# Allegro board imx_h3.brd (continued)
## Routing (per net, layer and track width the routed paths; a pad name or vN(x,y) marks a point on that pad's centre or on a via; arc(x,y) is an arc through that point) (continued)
LCD_D11_EMI: length 2.2
  TOP w0.1: J13.84 95.82,75.54 FL5.10
LCD_D12: length 81.3
  TOP w0.1: FL4.3 88.27,76.77 88.27,76.77 85.9,76.77 85.27,77.39 85.27,77.41 v1(84.99,77.41) ; v1(84.23,79.81) 84.2,79.81 83.8,80.22 83.8,80.45 83.58,80.67 83.58,81.72 84.13,82.27 RN7.5
  INT1 w0.1: v1(84.99,77.41) 84.09,77.41 83.74,77.06 83.74,71.46 80.49,68.22 80.19,68.22 79.69,68.22 79.07,68.22 78.24,67.38 77.03,67.38 76.68,67.03 76.68,66.87 75.69,65.88 75.59,65.88 75.59,65.87 75.25,65.87 75.25,65.88 66.71,65.88 66.71,65.87 66.13,65.87 65.98,65.87 65.74,65.87 65.39,65.87 65.38,65.87 61.93,65.87 61.6,65.87 60.6,65.87 60.01,65.87 56.9,68.99 53.15,68.99 52.67,68.51 v1(52.67,68.14) ; v1(51.05,63.58) 51.05,63.26 48.48,60.69 48.48,59.44 47.95,58.91 47.95,56.62 49.26,55.31 49.26,54.81 49.26,53.67 49.64,53.28 v1(49.74,53.28)
  BOTTOM w0.1: v1(51.05,63.58) 51.05,63.77 52.09,64.81 52.09,65.15 52.33,65.39 52.33,65.42 52.67,65.77 v1(52.67,68.14) ; v1(84.99,77.41) 84.95,77.41 84.7,77.66 84.7,78.44 84.23,78.92 v1(84.23,79.81) ; v1(49.74,53.28) 49.81,53.28 49.85,53.24 50.24,53.24
LCD_D12_EMI: length 2.5
  TOP w0.1: FL4.7 94.09,76.77 94.72,76.15 95.9,76.15 J13.86
LCD_D13: length 85.5
  TOP w0.1: v1(84.17,78.04) 85.05,78.04 86.12,76.97 88.18,76.97 88.19,76.97 92.46,76.97 92.5,77.01 92.58,77.01 FL4.4 ; v1(84.03,80.79) 84.03,81.35 84.63,81.95 RN7.6
  INT1 w0.1: v1(45.5,62.81) 45.53,62.78 45.61,62.78 50.92,68.09 50.98,68.09 51.21,68.32 51.21,68.38 52.22,69.38 56.82,69.38 56.82,69.39 57.06,69.39 60.17,66.27 60.77,66.27 61.43,66.27 61.76,66.27 66.55,66.27 66.55,66.28 74.76,66.28 74.77,66.28 74.85,66.28 75.25,66.68 76.13,66.68 76.38,66.93 76.38,67.01 76.95,67.58 78.16,67.58 78.99,68.41 79.61,68.41 80.41,68.42 83.54,71.55 83.54,77.41 v1(84.17,78.04)
  BOTTOM w0.1: v1(84.03,80.79) 83.83,80.58 83.83,78.39 v1(84.17,78.04) ; v1(45.5,62.81) 45.48,62.81 45.48,62.78 47.72,62.78 49.77,60.72 49.77,58.96 49.47,58.66 49.47,57.4 49.83,57.05 49.83,57.05 50.73,56.16 50.73,53.6 51.05,53.28 51.05,53.24
LCD_D13_EMI: length 2.4
  TOP w0.1: J13.88 95.7,76.84 94.71,76.84 94.38,77.17 FL4.8
LCD_D14: length 83
  TOP w0.1: FL4.5 91.79,77.57 91.59,77.38 v1(91.48,77.38) 91.32,77.21 88.45,77.21 86.64,79.02 86.64,80.17 85.13,81.69 RN7.7
  INT1 w0.1: v1(90.32,68.65) 90.25,68.58 86.95,68.58 85.31,66.94 85.11,66.94 81.84,63.67 81.2,63.67 80.2,63.67 79.58,63.05 78.64,63.05 78.4,62.81 78.06,62.81 78.06,62.81 77.37,62.81 77.37,62.81 76.75,62.81 76.75,62.81 75.61,62.81 75.61,62.81 74.53,62.81 74.53,62.81 73.2,62.81 73.2,62.81 71.65,62.81 71.65,62.81 70.66,62.81 70.66,62.81 61.04,62.81 61.04,62.81 59.38,62.81 59.38,62.81 58.96,62.81 58.96,62.81 58.37,62.81 57.5,63.67 57.49,63.67 57.25,63.91 54.08,63.91 52.9,65.09 51.2,65.09 49,62.89 48.85,62.89 v1(48.71,62.75)
  BOTTOM w0.1: v1(91.48,77.38) 91.12,77.02 91.12,70.53 90.67,70.07 90.67,69.12 90.37,68.82 90.37,68.7 v1(90.32,68.65) ; 51.05,54.03 51.03,54.04 51.03,56.13 49.92,57.25 49.91,57.25 49.67,57.49 49.67,58.57 49.98,58.87 49.98,61.48 v1(48.71,62.75)
LCD_D14_EMI: length 2.4
  TOP w0.1: J13.90 95.7,77.34 94.71,77.34 94.68,77.37 94.27,77.37 94.07,77.57 FL4.9
LCD_D15: length 73.9
  TOP w0.1: FL4.6 91.01,77.97 90.77,77.72 v1(90.77,77.62) 90.62,77.47 88.48,77.47 86.84,79.1 86.84,80.26 85.68,81.42 RN7.8
  INT1 w0.1: v1(52.19,58.96) 52.2,58.97 54.34,58.97 55.71,60.34 55.74,60.38 55.85,60.49 57.09,60.49 58.2,61.6 58.72,61.6 59.1,61.6 59.21,61.6 59.62,61.6 59.88,61.6 59.88,61.61 60.54,61.61 60.54,61.6 73.7,61.6 73.7,61.61 74.03,61.61 74.03,61.6 78,61.6 78.28,61.33 78.61,61.33 79.27,61.33 80.61,62.67 81.2,62.67 81.6,62.67 82.26,62.67 82.97,63.38 84.06,63.38 85.4,64.72 v1(85.4,64.75)
  BOTTOM w0.1: v1(52.19,58.96) 52.16,58.93 52.16,58.16 51.43,57.43 51.43,55.49 51.84,55.08 U1.U3 ; v1(90.77,77.62) 90.74,77.62 90.71,77.59 90.71,70.64 89.74,69.67 89.74,69.14 85.4,64.79 v1(85.4,64.75)
LCD_D15_EMI: length 2.4
  TOP w0.1: FL4.10 94.12,77.97 94.51,77.59 95.87,77.59 J13.92
LCD_D16: length 75.5
  TOP w0.1: RN6.1 87.04,89.4 87.04,79.19 88.56,77.67 89.61,77.67 90.09,78.15 v1(90.12,78.15) 90.13,78.15 90.46,78.48 91.66,78.48 92.38,79.2 92.75,79.2
  INT1 w0.1: v1(51.69,58.41) 51.69,58.43 51.58,58.54 51.58,58.92 52.03,59.37 52.05,59.37 52.8,60.12 52.8,60.37 52.79,60.38 52.79,60.72 52.8,60.73 52.8,60.94 53.35,61.5 54.89,61.5 55.37,61.97 57.46,61.97 57.6,61.84 57.92,61.84 57.96,61.8 58.72,61.8 59.12,61.8 59.54,61.8 59.8,61.81 59.8,61.81 60.62,61.81 60.62,61.81 73.62,61.81 73.62,61.81 74.11,61.81 74.11,61.81 76.03,61.81 76.03,61.81 76.33,61.81 76.33,61.81 78.08,61.81 78.36,61.53 79.19,61.53 80.53,62.87 80.86,62.87 81.28,62.87 81.68,62.87 82.18,62.87 82.92,63.62 83.17,63.62 83.17,63.61 83.65,63.61 85.43,65.4 v1(85.43,65.4)
  BOTTOM w0.1: v1(51.69,58.41) 51.62,58.34 51.62,57.89 51.23,57.51 51.23,57.04 51.23,57.04 51.23,55.33 51.45,55.12 51.45,53.55 51.77,53.24 51.84,53.24 ; v1(90.12,78.15) 90.12,77.83 89.75,77.47 89.75,71.68 89.43,71.35 89.43,69.52 85.45,65.54 85.45,65.43 v1(85.43,65.4)
LCD_D16_EMI: length 2.8
  TOP w0.1: 93.71,79.2 93.71,79.02 94.55,78.18 95.87,78.18 J13.94
LCD_D17: length 76.8
  TOP w0.1: v1(87.45,83.9) 87.45,79.06 88.62,77.89 89.17,77.89 v1(89.37,78.09) 90.1,78.82 91.37,78.82 92.15,79.61 FL3.4
  INT1 w0.1: v1(86.66,69.06) 86.57,69.06 86.53,69.1 86.15,69.1 84.83,67.78 84.83,67.22 81.68,64.07 80.03,64.07 79.41,63.45 78.47,63.45 78.23,63.21 75.45,63.21 75.45,63.21 74.69,63.21 74.69,63.21 73.04,63.21 73.04,63.21 71.82,63.21 71.82,63.21 70.49,63.21 70.49,63.21 61.2,63.21 61.2,63.21 58.79,63.21 56.62,65.38 55.59,65.38 55.58,65.38 55.08,65.38 55.08,65.38 54.39,65.38 54.27,65.25 v1(53.36,65.25) ; v1(49.36,59.81) 51.09,61.54 51.09,61.82 52.9,63.63 52.96,63.63 v1(53,63.68)
  BOTTOM w0.1: v1(49.36,59.81) 49.27,59.72 49.27,57.65 49.27,57.32 49.77,56.82 49.77,54.08 50.31,53.54 50.39,53.54 50.74,53.19 50.74,53.11 50.92,52.93 51.35,52.93 U1.R3 ; v1(87.45,83.9) 87.45,84.44 R207.1 ; v1(89.37,78.09) 88.45,77.17 88.45,73.39 88.45,72.06 86.73,70.34 86.73,69.13 v1(86.66,69.06) ; v1(53,63.68) 53,64.32 53.18,64.5 53.18,65.07 v1(53.36,65.25)
LCD_D17_EMI: length 2.7
  TOP w0.1: J13.96 95.7,78.84 94.46,78.84 94.09,79.21 94.09,79.31 93.95,79.44 93.87,79.44 FL3.8
LCD_D18: length 73.6
  TOP w0.1: RN6.3 88.09,89.4 88.09,87.52 87.9,87.33 87.9,79.15 88.46,78.59 88.46,78.59 88.76,78.29 v1(88.8,78.29) 89.65,79.15 90.99,79.15 91.84,80 92.75,80
  INT1 w0.1: v1(84.57,62.01) 84.16,62.42 84.16,62.74 83.92,62.98 83.2,62.98 82.48,62.27 81.43,62.27 81.03,62.27 80.78,62.27 79.44,60.93 78.77,60.93 78.11,60.93 77.84,61.21 60.38,61.21 60.38,61.21 60.04,61.21 60.04,61.21 59.78,61.21 59.37,61.2 59.37,61.2 58.81,61.2 57.7,60.09 57.26,60.09 57.26,60.09 56.25,60.09 56.24,60.08 56.02,60.08 54.5,58.57 52.99,58.57 52.28,57.86 52.28,56.79 v1(52.18,56.69)
  BOTTOM w0.1: U1.U4 52.64,54.65 52.55,54.75 52.55,55.38 52.18,55.75 v1(52.18,56.69) ; v1(84.57,62.01) 84.57,62.02 84.97,62.42 84.97,65.68 86.12,66.84 86.12,70.03 88.25,72.15 88.25,72.81 88.25,77.75 v1(88.8,78.29)
LCD_D18_EMI: length 2.6
  TOP w0.1: 95.91,79.14 95.77,79.28 94.44,79.28 94.09,79.62 94.09,79.7 93.95,79.84 93.87,79.84 93.71,80
LCD_D19: length 70
  TOP w0.1: FL3.6 91.76,80.41 90.7,79.35 89.27,79.35 v1(89.22,79.31) 89,79.31 88.4,79.9 88.4,84.15 v1(88.35,84.2)
  INT1 w0.1: v1(51.88,57.28) 51.88,57.74 52.9,58.77 54.42,58.77 55.92,60.27 55.93,60.28 56.16,60.28 56.17,60.29 57.17,60.29 57.18,60.3 57.4,60.3 58.5,61.4 58.64,61.4 59.02,61.4 59.11,61.4 59.29,61.4 59.7,61.4 59.96,61.41 59.96,61.41 60.46,61.41 60.46,61.41 77.92,61.41 78.19,61.13 78.69,61.13 79.36,61.13 80.7,62.47 81.11,62.47 81.51,62.47 82.4,62.47 83.11,63.18 84.05,63.18 84.55,62.68 v1(84.56,62.68)
  BOTTOM w0.1: v1(51.88,57.28) 51.73,57.14 51.73,55.61 52.3,55.04 52.3,53.54 52.61,53.24 52.64,53.24 ; v1(84.56,62.68) 84.45,62.8 84.45,65.45 85.93,66.93 85.93,70.11 88.05,72.23 88.05,72.9 88.05,78.12 89.2,79.27 89.2,79.28 v1(89.22,79.31) ; v1(88.35,84.2) 88.3,84.25 88.3,85.35 87.96,85.69 R107.1
LCD_D19_EMI: length 2.5
  TOP w0.1: FL3.10 93.86,80.41 94.5,79.77 95.78,79.77 95.91,79.64
LCD_D20: length 80.1
  TOP w0.1: RN6.5 89.1,89.4 89.1,84.25 88.6,83.75 88.6,79.98 88.87,79.71 90.03,79.71 90.05,79.73 v1(90.05,79.75) 90.34,79.75 92.17,81.58 FL2.3
  INT1 w0.1: v1(53.63,62.62) 53.61,62.6 52.73,62.6 51.71,61.59 51.71,61.34 51.71,61 49.38,58.68 49.38,56.78 50.34,55.82 50.35,55.82 51.11,55.06 51.11,54.51 52.25,53.37 v1(52.25,52.92) ; v1(85.23,67.54) 85.2,67.51 85.2,67.3 81.76,63.87 81.28,63.87 80.12,63.87 79.5,63.25 78.56,63.25 78.31,63.01 75.53,63.01 75.53,63 74.61,63 74.61,63.01 73.12,63.01 73.12,63 71.74,63 71.74,63.01 70.58,63.01 70.58,63 61.12,63 61.12,63.01 59.3,63.01 59.3,63 59.04,63 59.04,63.01 58.45,63.01 57.58,63.87 57.57,63.87 56.26,65.18 55.51,65.18 55.5,65.18 55.17,65.18 55.16,65.18 54.47,65.18 54.09,64.79 v1(53.78,64.79)
  BOTTOM w0.1: U1.R4 52.3,52.78 52.3,52.87 v1(52.25,52.92) ; v1(85.23,67.54) 85.2,67.57 85.2,69.65 85.62,70.07 85.62,70.09 87.84,72.31 87.84,78.21 88.82,79.17 88.82,79.63 88.9,79.72 90.01,79.72 v1(90.05,79.75) ; v1(53.63,62.62) 53.63,64.64 v1(53.78,64.79)
LCD_D20_EMI: length 2.9
  TOP w0.1: FL2.7 93.71,81.34 94.71,80.34 95.7,80.34 95.91,80.14
LCD_D21: length 68.6
  TOP w0.1: v1(89.57,84.8) 89.57,84.41 88.95,83.79 88.95,80.57 89.07,80.45 v1(89.07,80.15) 89.19,80.15 89.21,80.12 89.53,80.12 91.38,81.97 FL2.4
  INT1 w0.1: v1(83.17,61.86) 80.93,61.86 79.61,60.53 78.94,60.53 78.39,60.53 77.95,60.53 77.67,60.81 60.21,60.81 60.01,60.6 59.86,60.46 59.86,60.45 59.61,60.19 58.65,60.19 57.16,58.71 55.73,58.71 54.55,57.53 v1(52.88,57.53)
  BOTTOM w0.1: R100.1 89.57,86.52 v1(89.57,84.8) ; v1(52.88,57.53) 52.59,57.24 52.59,56.3 53.43,55.46 53.43,54.05 53.45,54.03 ; v1(83.17,61.86) 83.38,61.86 83.94,62.43 83.94,68.69 85.42,70.16 85.42,70.17 87.65,72.39 87.65,78.29 88.62,79.26 88.62,79.94 88.83,80.16 89.07,80.16 v1(89.07,80.15)
LCD_D21_EMI: length 2.9
  TOP w0.1: 95.91,80.64 95.7,80.84 94.71,80.84 94.42,81.14 94.42,81.39 93.83,81.97 FL2.8
LCD_D22: length 72.2
  TOP w0.1: RN6.7 90.1,89.4 90.1,84.36 89.2,83.47 89.2,81 89.34,80.86 v1(89.4,80.86) 89.61,80.86 91.13,82.38 FL2.5
  INT1 w0.1: v1(53.03,55.03) 52.96,55.1 52.96,55.15 52.59,55.52 52.59,56.86 52.48,56.97 52.48,57.78 53.07,58.37 54.59,58.37 56.1,59.88 56.33,59.88 58.05,59.88 58.57,60.39 59.52,60.39 59.81,60.69 59.81,60.69 60.12,61 77.75,61 78.03,60.73 78.31,60.73 78.86,60.73 79.52,60.73 80.86,62.07 81.35,62.07 82.58,62.07 83.09,62.58 v1(83.52,62.58)
  BOTTOM w0.1: 53.45,53.24 53.45,53.26 53.03,53.68 v1(53.03,55.03) ; v1(89.4,80.86) 89.39,80.86 89.04,80.86 88.41,80.24 88.41,79.34 87.45,78.38 87.45,72.48 85.22,70.25 85.22,70.25 83.74,68.77 83.74,62.78 83.54,62.58 v1(83.52,62.58)
LCD_D22_EMI: length 2.8
  TOP w0.1: 95.91,81.14 95.7,81.34 94.71,81.34 94.62,81.44 94.62,81.55 93.79,82.38 FL2.9
LCD_D23: length 74.3
  TOP w0.1: 92.75,82.78 91.03,82.78 89.92,81.67 v1(89.74,81.67) 89.74,81.96 89.62,82.08 89.62,82.7 90.42,83.5 90.44,83.5 v1(90.64,83.69)
  INT1 w0.1: v1(83.34,64.01) 83.04,64.01 82.09,63.07 81.76,63.07 81.36,63.07 80.95,63.07 80.45,63.07 79.11,61.73 78.44,61.73 78.17,62 76.41,62 76.41,62.01 75.94,62.01 75.94,62 74.2,62 74.2,62.01 73.53,62.01 73.53,62 71.32,62 71.32,62.01 70.99,62.01 70.99,62 60.71,62 60.71,62.01 59.71,62.01 59.71,62 59.45,62 59.04,62 58.04,62 57.17,62.87 54.45,62.87 53.69,62.11 53.45,62.11 52.55,61.21 52.55,61.14 51.87,60.46 51.87,60.36 49.58,58.08 49.58,57.19 51.52,55.26 51.52,54.76 52.89,53.38 52.89,53.26 53.07,53.09 53.07,52.87 v1(53.07,52.87)
  BOTTOM w0.1: v1(90.64,83.69) 90.67,83.73 90.67,84.9 90.92,85.14 90.92,85.42 91.39,85.89 91.39,86.67 R106.1 ; v1(89.74,81.67) 89.45,81.67 88.21,80.43 88.21,79.43 87.25,78.46 87.25,72.56 83.54,68.85 83.54,64.22 v1(83.34,64.01) ; v1(53.07,52.87) 53.07,52.8 53.44,52.44 53.45,52.44
LCD_D23_EMI: length 2.7
  TOP w0.1: 93.71,82.78 93.79,82.78 94.09,82.47 94.09,82.44 94.68,81.84 95.7,81.84 95.91,81.64
LCD_DOTCLK: length 1.9
  TOP w0.1: R87.1 101.64,60.65 J13.43
LCD_ENABLE: length 14
  TOP w0.1: R84.1 106.53,81.66 106.25,81.38 106.16,81.38 105.87,81.09 105.87,81.03 v1(105.9,81.03) ; 95.91,83.64 97.86,83.64 98.25,84.02 99.56,84.02 99.64,84.11 v1(99.69,84.11) 99.94,83.86 99.94,83.77 100.19,83.51 100.19,82.44 100.13,82.38 100.13,81.64 v1(100.03,81.53)
  BOTTOM w0.1: v1(105.9,81.03) 101.12,81.03 100.61,81.53 v1(100.03,81.53)
LCD_HSYNC: length 8.6
  TOP w0.1: v1(103.25,83.25) 104.03,83.25 ; v1(99.76,83.36) 99.31,83.82 98.33,83.82 97.65,83.14 95.91,83.14
  BOTTOM w0.1: v1(99.76,83.36) 100.07,83.36 100.19,83.25 v1(103.25,83.25)
LCD_PWR_EN: length 101.5
  TOP w0.1: J13.79 102.86,74.63 102.9,74.68 v1(103.13,74.68) ; v1(44.53,57.91) 44.66,58.04 45.67,58.04 46.13,57.57 46.13,56.55 48.52,54.17 48.52,53.4 50.39,51.52 50.39,50.89 51.25,50.03 52.61,50.03 52.78,49.87 53.35,49.87 53.88,50.39 v1(53.89,50.39) ; v1(97.52,67.33) 95.44,65.26 94.59,65.26 89.63,60.3 85.15,60.3 84.4,61.05 v1(83.37,61.05)
  INT1 w0.1: v1(80.46,69.84) 80.38,69.77 80.38,69.22 80.14,68.99 74.31,68.99 72.4,67.07 66.21,67.07 66.21,67.07 61.43,67.07 60.5,67.07 57.38,70.19 51,70.19 43.77,62.96 43.77,59.07 44.55,58.28 44.55,57.92 44.54,57.91 v1(44.53,57.91) ; v1(97.52,67.33) 97.48,67.36 97.48,69.03 v1(103.13,74.68)
  BOTTOM w0.1: U1.M6 v1(53.89,50.39) ; v1(83.37,61.05) 83.09,61.05 81.7,62.44 81.7,64.15 80.65,65.2 80.65,66.77 80.46,66.97 v1(80.46,69.84)
LCD_RD_E: length 85.2
  TOP w0.1: v1(104.54,88.53) 104.56,88.53 104.67,88.41 FL8.5
  INT1 w0.1: v1(52.31,52.05) 52.3,52.07 52.29,52.07 52.05,52.31 52,52.31 51.62,52.69 51.62,53.25 50.71,54.16 50.71,54.8 48.98,56.53 48.98,57.06 48.98,57.07 48.98,58.84 51.31,61.17 51.31,61.75 52.83,63.27 57.34,63.27 58.17,62.44 58.2,62.4 59.29,62.4 59.29,62.41 59.55,62.41 59.55,62.41 60.87,62.41 60.87,62.41 70.83,62.41 70.83,62.41 71.49,62.41 71.49,62.41 73.37,62.41 73.37,62.41 74.36,62.41 74.36,62.41 75.78,62.41 75.78,62.41 76.58,62.41 76.58,62.41 78.33,62.41 78.61,62.13 78.94,62.13 80.28,63.47 81.11,63.47 81.53,63.47 81.93,63.47 85.2,66.74 85.4,66.74 86.31,67.65 92.25,67.65 92.8,68.2 92.85,68.2 94.47,69.82 94.47,70.08 94.47,70.08 94.61,70.22 94.65,70.26 94.88,70.49 95.08,70.7 95.29,70.9 96.47,72.08 96.47,83.13 101.12,87.78 102.49,87.78 103.23,88.53 v1(104.54,88.53)
  BOTTOM w0.1: v1(52.31,52.05) 52.33,52.04 52.33,51.95 U1.P4
LCD_RD_E_CON: length 1.2
  TOP w0.1: R90.1 105.75,84.08 R85.2
LCD_RD_E_EMI: length 3
  TOP w0.1: R91.2 R90.2 105.06,85.88 105.06,86.33 104.67,86.72 FL8.9
LCD_RS: length 99.9
  TOP w0.1: v1(82.92,73.39) 82.94,73.39 84.34,74.79 85.15,74.79 85.38,74.57 v1(85.5,74.57) ; v1(102.05,88.39) 102.11,88.45 103.32,88.45 FL8.3
  INT1 w0.1: v1(82.92,73.39) 82.55,73.02 82.55,72.6 80.34,70.39 80.16,70.39 78.95,69.19 74.23,69.19 73.16,68.12 70.19,68.12 69.35,67.28 66.13,67.28 66.13,67.27 65.97,67.27 60.59,67.27 57.47,70.4 51.34,70.4 50.92,70.4 43.03,62.51 43.03,58.57 44.51,57.09 45.09,57.09 47.85,54.33 47.85,51.19 48.97,50.07 49.39,50.07 49.65,49.81 51.62,49.81 52.12,50.32 52.12,50.37 v1(52.23,50.49) ; v1(85.5,74.57) 85.52,74.57 85.52,74.65 85.71,74.65 85.77,74.59 86.11,74.59 86.34,74.82 86.34,74.88 86.41,74.94 95.06,74.94 95.73,75.62 95.73,84.87 98.69,87.82 99.93,87.82 100.22,88.11 100.84,88.11 101.12,88.39 v1(102.05,88.39)
  BOTTOM w0.1: v1(52.23,50.49) 52.23,50.44 U1.M4
LCD_RS_CON: length 2.1
  TOP w0.1: 101.63,84.64 103.4,84.64 R86.1
LCD_RS_EMI: length 35.4
  TOP w0.1: 103.87,85.61 103.76,85.5 v1(103.34,85.5) ; 103.87,85.61 FL8.7 ; 103.87,85.61 104.63,84.85 ; R87.2 104.45,60.65 103.83,61.26 103.15,61.26 v1(103.13,61.24)
  INT1 w0.1: v1(103.13,61.24) 102.66,61.7 102.66,70.67 103.94,71.94 103.94,77.39 100.2,81.13 99.86,81.13 98.96,82.03 98.96,84.06 99.62,84.72 102.56,84.72 v1(103.34,85.5)
LCD_RW_B: length 98.9
  TOP w0.1: v1(100.75,88.85) 100.76,88.86 103.39,88.86 104.11,88.14 104.11,88.06 FL8.4 ; v1(82.87,74.13) 83.08,74.13 83.94,75 85.94,75 v1(85.94,74.99)
  INT1 w0.1: v1(82.87,74.13) 82.53,74.13 79.34,70.95 72.28,70.95 70.16,68.83 70.16,68.46 69.17,67.47 65.78,67.47 65.78,67.47 60.67,67.47 57.55,70.59 51.42,70.59 50.83,70.6 42.83,62.59 42.83,58.48 44.43,56.88 45.01,56.88 47.65,54.24 47.65,51 48.94,49.71 v1(48.94,49.67) ; v1(85.94,74.99) 85.94,75.04 86.09,75.19 95.03,75.19 95.54,75.7 95.54,85.09 98.46,88.02 99.81,88.02 100.59,88.8 100.7,88.8 v1(100.75,88.85)
  BOTTOM w0.1: v1(48.94,49.67) 48.95,49.67 48.96,49.66 48.96,49.34 49.67,48.64 49.86,48.64 50.06,48.44 U1.K1
LCD_RW_B_EMI: length 6
  TOP w0.1: v1(105.69,83.43) 105.61,83.43 105.35,83.17 105.12,83.17 R89.2 105.04,82.84 R88.2 ; v1(104.66,86.03) 104.66,86.17 104.27,86.56 FL8.8
  BOTTOM w0.1: v1(104.66,86.03) 104.77,86.03 104.88,85.92 104.88,84.67 105.54,84 105.54,83.46 105.58,83.43 v1(105.69,83.43)
LCD_VSYNC: length 12.6
  TOP w0.1: 95.91,82.14 97.46,82.14 98.38,83.05 99.15,83.05 99.4,82.8 v1(99.4,82.51) ; v1(106.52,83.52) 106.52,84.1 R91.1
  BOTTOM w0.1: v1(99.4,82.51) 99.54,82.51 99.82,82.79 99.97,82.79 100.13,82.63 105.78,82.63 106.52,83.36 v1(106.52,83.52)
LCD_WR_RWN_CON: length 2.2
  TOP w0.1: 101.63,82.14 101.68,82.18 103.22,82.18 103.51,82.47 R88.1
LI-ION_BATTERY: length 95.7
  TOP w0.1: 74.17,35.57 Q14.4 74.58,35.92 ; 66.96,30.89 J17.1 67.86,29.99 ; J13.67 J13.69
  TOP w0.3: C263.1 J13.65 J13.67 ; J13.71 J13.69 104.06,72.13 C289.1
  TOP w0.5: Q14.4 74.3,35.84 74.2,35.84 73.79,36.25 72.72,36.25 ; 72.72,36.25 70.9,36.25 69.98,35.32 69.98,33.81 67.86,31.69 J17.1 68.18,31.21 68.18,32.47 68.19,32.47 68.19,33.42 66.92,34.68 65.93,34.68 C127.1 64.2,35.7 C124.1 63.66,36.25 63.53,36.25 63.3,36.47 63.3,36.63 63,36.94 63,37.7 C126.1 ; 72.72,36.25 72.72,37.6 73.72,38.6 74.52,38.6 74.98,39.06 74.98,39.65 79.06,43.72 v1(79.06,44.09) ; C125.1 61.73,37.89 v1(61.73,37.31) ; v1(61.73,37.31) 61.65,37.24 C128.1 ; v1(61.73,37.31) 61.72,37.32 61.72,38.22 61.37,38.58 v1(61.37,38.68) ; v1(61.73,37.31) 62.16,37.75 C126.1 ; C126.1 63.08,37.78 ; v1(90.34,65.88) 90.36,65.88 90.76,66.28 95.34,66.28 97.93,68.87 97.93,70.66 98.29,71.03 100.24,71.03 100.34,71.12 101.62,71.12 J13.65
  INT1 w0.5: v1(90.34,65.88) 89.81,65.34 89.18,65.34 82.7,58.85 82.35,58.85 81.27,57.77 81.27,49.35 80.92,49 80.92,47.19 80.51,46.78 80.51,46.72 79.45,45.66 79.45,45.66 79.06,45.28 v1(79.06,44.09)
  BOTTOM w0.25: v1(61.37,38.68) 61.4,38.68 61.75,39.02 61.75,41.73 61.45,42.03 61.45,42.03
  BOTTOM w0.3: 61.45,41.24 61.45,38.35 61.27,38.18 61.27,37.62 61.58,37.31 v1(61.73,37.31) 61.73,37.49 61.85,37.61
  vias: v1(61.39,39.3)
LRADC1: length 0.6
  BOTTOM w0.1: 56.64,42.84 56.64,42.75 56.34,42.46 v1(56.29,42.46)
LRADC2: length 114.8
  TOP w0.1: v1(55.48,42.41) 55.45,42.38 55.45,41.66 54.63,40.84 53.69,40.84 53.03,40.84 50.34,38.14 48.56,38.14 48.27,37.86 v1(48.27,37.72) ; v1(87.36,36.62) 86.81,36.62 85.65,35.47 85.65,33.9 79.45,27.7 64.74,27.7 61.31,27.69 v1(61.3,27.72) ; v1(99.92,78.9) 99.92,78.94 100.32,79.34 100.32,79.41 100.54,79.64 101.63,79.64
  INT1 w0.1: v1(99.92,78.9) 99.76,78.9 98.65,77.79 98.65,73.13 95.27,69.75 95.27,69.47 91.58,65.78 89.99,64.19 88.26,62.45 88.21,62.45 84.79,59.03 84.6,59.03 83.32,57.75 83.3,57.75 82.08,56.53 82.08,49.35 82.08,49.35 82.08,49.02 82.08,49.01 82.08,47.94 82.61,47.41 83.45,47.41 85.87,44.99 85.87,43.21 85.87,43.21 85.87,41.36 85.87,40.48 85.97,40.38 85.97,40.37 87.08,39.26 87.08,37.71 87.36,37.43 v1(87.36,36.62)
  BOTTOM w0.1: v1(55.48,42.41) 55.38,42.41 55.39,42.41 55.81,42.84 55.84,42.84 ; C139.1 61.31,27.73 v1(61.3,27.72) 61.3,27.72 61.22,27.64 57.66,27.64 51.19,34.12 50.08,34.12 48.72,35.48 48.72,35.98 48.53,36.16 48.53,36.25 48.27,36.51 v1(48.27,37.72)
LRADC3: length 119
  TOP w0.1: v1(88.05,36.53) 88.05,29.01 86.48,27.45 61.66,27.45 61.52,27.31 61.03,27.31 60.47,27.88 60.47,28.1 v1(60.46,28.12) ; J13.95 100.62,78.63 100.31,78.33 100.31,78.13 99.93,77.75 v1(99.93,77.68) ; v1(56.27,43.26) 56.27,43.26 56.27,43.04 56.69,42.62 56.69,42.29 56.46,42.05 56.12,42.05 54.71,40.63 53.12,40.63 50.23,37.75 48.96,37.75 v1(48.91,37.69)
  INT1 w0.1: v1(99.93,77.68) 99.09,76.84 99.09,72.93 96.51,70.34 96.51,69.56 95.67,68.72 95.67,68.36 94.06,66.75 93.11,66.75 91.65,65.28 88.42,62.05 88.38,62.05 84.96,58.63 84.77,58.63 82.52,56.38 82.52,48.64 83.44,47.72 83.44,47.7 86.07,45.08 86.07,43.29 86.07,41.44 86.07,40.56 87.28,39.35 87.28,37.8 88.05,37.03 v1(88.05,36.53)
  BOTTOM w0.1: v1(56.27,43.26) 56.35,43.26 56.64,43.56 U1.D9 ; C138.1 60.45,28.13 v1(60.46,28.12) 60.39,28.05 57.6,28.05 51.34,34.31 50.17,34.31 48.96,35.52 48.96,36.09 48.74,36.32 48.74,36.34 48.73,36.34 48.59,36.49 48.59,37.26 48.91,37.58 v1(48.91,37.69)
LRADC4: length 103.7
  TOP w0.1: v1(58.78,32.44) 58.78,32.78 59.02,33.02 59.02,35.26 59.02,35.26 59.02,37.73 59.02,37.73 59.02,38.08 60.08,39.15 60.39,39.46 60.39,42.48 60.42,42.5 60.42,43.09 v1(60.3,43.21) ; 101.63,80.14 100.43,80.14 99.91,79.61 v1(99.91,79.51)
  INT1 w0.1: v1(99.91,79.51) 99.76,79.51 98.45,78.2 98.45,73.21 95.54,70.3 95.07,69.83 95.07,69.55 91.5,65.98 89.91,64.39 88.17,62.65 88.13,62.65 84.71,59.23 84.52,59.23 83.24,57.96 83.21,57.96 81.88,56.62 81.88,54.03 81.88,47.86 82.53,47.21 83.37,47.21 85.65,44.93 85.65,40.33 86.57,39.41 86.57,38.02 86.57,38.01 86.57,35.36 85.64,34.43 85.64,31.09 85.25,30.7 85.25,30.34 v1(85.09,30.19)
  BOTTOM w0.1: C137.1 58.78,32.99 v1(58.78,32.44) 60.2,32.44 62.44,30.19 62.44,29.64 63.15,28.94 83.48,28.94 84.57,30.02 84.93,30.02 v1(85.09,30.19) ; v1(60.3,43.21) 60.24,43.26 60.22,43.26 U1.D13 59.85,43.63
LRADC5: length 67
  TOP w0.1: 101.63,79.14 101.59,79.1 100.54,79.1 100.33,78.88 100.33,78.72 v1(99.9,78.29) ; v1(61.06,44.08) 61.07,44.08 61.07,44.07 61.5,43.64 63.19,43.64 63.27,43.72 63.6,43.72 63.83,43.5 63.85,43.5 63.89,43.46 63.89,43.22 63.96,43.16 64.45,43.16 64.84,43.54 66.5,43.54 66.89,43.15 73.89,43.15 75.94,45.2 76.88,45.2 76.9,45.22 79.09,45.22 79.9,46.03 80.92,46.03 v1(82.73,47.85) 82.52,48.07 C136.1
  INT1 w0.1: v1(99.9,78.29) 99.73,78.29 98.85,77.41 98.85,73.05 95.47,69.67 95.47,68.44 94.19,67.16 93.25,67.16 91.66,65.58 90.08,63.99 88.34,62.25 88.3,62.25 84.88,58.83 84.68,58.83 83.41,57.56 83.38,57.56 82.28,56.45 82.28,49.43 82.28,49.43 82.28,48.6 82.62,48.26 82.62,47.97 v1(82.73,47.85)
  BOTTOM w0.1: v1(61.06,44.08) 61.07,44.08 61.07,43.96 61.39,43.63 61.45,43.63
LRADC6: length 82.9
  TOP w0.1: 94.05,59.13 J13.38 ; 94.05,59.13 94.03,59.15 84.06,59.15 v1(83.96,59.25) ; 94.05,59.13 93.88,58.97 C135.1 ; v1(63.06,29.8) 63.05,29.8 63.05,29.79 63.02,29.82 63.02,29.96 61.4,31.58 61.4,33.21 60.66,33.94 60.23,33.94 59.62,34.56 59.62,37.62 60.66,38.66 60.73,38.66 v1(60.73,38.66)
  INT1 w0.1: v1(84.54,30.94) 85.44,31.84 85.44,34.51 86.37,35.45 86.37,37.94 86.37,37.95 86.37,39.32 85.41,40.28 85.41,44.88 83.29,47 82.43,47 81.68,47.76 81.68,53.62 81.68,56.7 83.9,58.93 83.9,59.25 v1(83.96,59.25)
  BOTTOM w0.1: v1(60.73,38.66) 60.76,38.66 60.95,38.84 60.95,39.74 60.95,39.74 60.95,40.25 60.95,40.25 60.95,42.16 60.94,42.16 60.94,42.54 60.64,42.84 ; v1(63.06,29.8) 63.05,29.8 63.05,29.79 63.16,29.79 63.82,29.13 82.74,29.13 v1(84.54,30.94)
MIC: length 8.3
  BOTTOM w0.3: U19.15 107.35,33.69 108.49,32.55 110.84,32.55 C159.1 C270.1 C299.2
MIC_BIAS: length 11.5
  TOP w0.3: J16.3 108.96,28.84 109.95,27.85 109.95,26.91 C300.1 111.79,26.7 R209.1
  BOTTOM w0.3: J16.3 108.48,29.37 C158.1 C269.1 108.48,31.49 106.78,33.19 U19.16
MODEM_GND: length 25
  TOP w0.5: U35.S1 U35.S4
  BOTTOM w0.3: 73.2,12.28 U35.S1 73.2,12.1 74.73,10.56 77,10.56 U35.S2 ; U35.S4 75.92,19.21 U35.4 78.64,18.94 U35.S3
  BOTTOM w0.5: C301.2 78.25,18.82 U35.S3 79.64,19.21 80.82,18.02 L26.2
MODEM_VBUS_EN: length 42.6
  TOP w0.1: v1(55.52,44.05) 55.51,44.05 55.13,43.67 54.84,43.67 54.84,43.67 54.5,43.67 54.49,43.67 53.63,43.67 53.61,43.64 52.93,43.64 52.7,43.41 52.7,43.37 52.37,43.05 51.41,43.05 50.3,41.94 48.73,41.94 47.72,40.94 41.46,40.94 39.58,39.05 39.58,38.42 39.2,38.04 35.64,38.04 34.72,38.97 31.88,38.97 v1(31.65,39.21)
  BOTTOM w0.1: v1(55.52,44.05) 55.5,44.04 55.5,43.97 55.16,43.63 55.05,43.63 ; v1(31.65,39.21) 31.52,39.34 29.87,39.34 29.83,39.3 29.5,39.3 29.36,39.44 28.31,39.44 27.07,38.2 27.07,36.95 26.98,36.86 26.98,36.84 25.75,35.62 25.75,35.3 25.33,34.88 24.83,34.88 23.59,33.64 U31.1
NAND_ALE: length 28.4
  TOP w0.1: v1(53.84,52.04) 53.84,52.34 53.5,52.69 53.5,53.09 53,53.59 52.97,53.59 51.72,54.84 51.72,55.34 49.92,57.14 49.92,57.15 49.67,57.39 49.67,57.83 51.24,59.4 51.49,59.4 v1(51.56,59.47)
  BOTTOM w0.1: U1.P6 53.88,52 53.88,52 v1(53.84,52.04) ; U5.17 42.56,67.03 42.62,66.97 46.08,66.97 51.32,61.72 51.32,59.81 51.62,59.51 51.62,59.49 51.6,59.47 v1(51.56,59.47)
NAND_CE_B: length 28.6
  TOP w0.1: v1(50.68,57.75) 50.69,57.74 50.69,57.28 52.12,55.85 52.12,55.04 53.77,53.39 53.95,53.39 54.34,53 54.34,52.61 54.24,52.52 54.24,51.76 54.52,51.49 54.52,51.36 v1(54.69,51.19)
  BOTTOM w0.1: v1(50.68,57.75) 50.68,57.76 50.67,57.77 50.67,61.66 48.84,63.5 43.08,63.5 43.06,63.52 40.8,63.52 40.31,63.02 U5.9 36.69,63.02 36.12,63.59 R25.2 ; 55.05,50.84 v1(54.69,51.19)
NAND_CLE: length 26.7
  TOP w0.1: v1(51.2,58.05) 51.2,58.01 51.2,58.01 51.2,57.05 52.32,55.93 52.32,55.12 53.85,53.59 54.03,53.59 54.53,53.09 54.54,53.09 54.54,53.09 54.55,53.08 54.55,52.22 54.65,52.12 v1(54.65,52.05)
  BOTTOM w0.1: v1(54.65,52.05) 54.7,52.05 55.05,51.71 55.05,51.63 ; v1(51.2,58.05) 51.2,58.07 51.12,58.15 51.12,61.64 46.23,66.53 U5.16
NAND_DAT0: length 17.5
  BOTTOM w0.1: U1.U8 55.84,54.8 54.82,55.83 54.82,56.37 54.82,56.71 54.82,56.71 54.82,57.21 54.82,57.21 54.82,57.48 55.04,57.7 55.04,58.14 55.04,58.14 55.04,59.52 55.04,64.22 54.73,64.53 54.73,66.84 54.74,66.85 54.74,67.72 55.03,68.01 55.03,68.04 55.52,68.53 U5.29
NAND_DAT1: length 18.8
  TOP w0.1: v1(55.83,68.1) 55.62,68.31 54.76,68.31 v1(54.63,68.18)
  BOTTOM w0.1: 55.84,53.24 55.84,53.46 55.46,53.84 55.46,54.91 54.62,55.75 54.62,56.62 54.62,56.63 54.62,57.29 54.62,57.29 54.62,57.56 54.84,57.78 54.84,58.82 54.84,58.82 54.84,59.1 54.84,59.1 54.84,64.14 54.53,64.45 54.53,68.08 v1(54.63,68.18) ; v1(55.83,68.1) 55.99,68.1 56.07,68.03 U5.30
NAND_DAT2: length 18.2
  BOTTOM w0.1: U1.R8 55.84,52.52 56.27,52.94 56.27,54.67 55.02,55.91 55.02,56.29 55.02,56.79 55.02,56.79 55.02,57.14 55.02,57.14 55.02,57.4 55.24,57.62 55.24,58.22 55.24,58.23 55.24,59.43 55.24,63.93 55.24,64.3 54.93,64.61 54.93,66.75 55.7,67.53 U5.31
NAND_DAT3: length 16.8
  TOP w0.1: v1(55.65,65.78) 55.53,65.9 54.16,65.9 v1(54,65.75)
  BOTTOM w0.1: v1(55.65,65.78) 55.65,66.27 56.41,67.03 U5.32 ; 55.05,54.03 55.05,54.97 54.42,55.59 54.42,56.54 54.42,56.54 54.42,57.39 54.42,57.39 54.42,57.64 54.64,57.86 54.64,58.31 54.63,58.31 54.63,64 54.2,64.44 54.2,65.54 v1(54,65.75)
NAND_DAT4: length 13
  TOP w0.1: v1(55.84,62.47) 55.79,62.52 55.15,62.52 54.49,61.87 54.17,61.87 v1(54.12,61.92)
  BOTTOM w0.1: v1(55.84,62.47) 55.9,62.52 U5.41 ; 55.05,53.24 55.05,53.41 54.61,53.84 54.61,55.12 54.22,55.51 54.22,56.46 54.22,56.46 54.22,57.46 54.22,57.46 54.22,57.73 54.43,57.94 54.43,61.49 54.12,61.81 v1(54.12,61.92)
NAND_DAT5: length 11.9
  TOP w0.1: v1(55.39,52.86) 55.49,52.97 55.49,55.28 55.24,55.54 55.24,56.78 v1(55.42,56.96)
  BOTTOM w0.1: v1(55.42,56.96) 55.42,56.96 55.39,56.99 55.39,57.48 55.44,57.53 55.44,57.87 55.44,58.31 55.44,58.31 55.44,59.35 55.44,59.68 55.44,60.01 55.44,61.69 55.77,62.02 U5.42 ; v1(55.39,52.86) 55.39,52.8 55.05,52.46 55.05,52.44
NAND_DAT6: length 11.6
  TOP w0.1: v1(55.87,61.51) 55.64,61.51 55.09,60.97 53.74,60.97 53.62,61.09 v1(53.59,61.09)
  BOTTOM w0.1: U1.U6 54.24,55.06 54.01,55.29 54.01,59.59 53.59,60.01 v1(53.59,61.09) ; U5.43 55.87,61.52 v1(55.87,61.51)
NAND_DAT7: length 12.3
  TOP w0.1: v1(53.19,60.55) 53.65,60.55 53.85,60.75 55.75,60.75 v1(55.91,60.91)
  BOTTOM w0.1: v1(55.91,60.91) 55.92,60.92 56.28,60.92 56.39,61.02 U5.44 ; v1(53.19,60.55) 53.19,60.54 53.17,60.53 53.17,60.15 53.8,59.53 53.8,54.06 54.19,53.66 54.19,53.29 54.24,53.24
NAND_RB_B: length 26.7
  TOP w0.1: v1(48.38,58.12) 48.38,56.77 49.84,55.31 49.84,54.19 51.65,52.38 51.65,52.38 51.84,52.19 51.84,51.92 52.12,51.65 53.35,51.65 53.76,51.24 53.84,51.24 v1(53.84,51.24)
  BOTTOM w0.1: v1(48.38,58.12) 48.24,58.26 48.24,61.67 47.9,62 47.87,62 47.39,62.49 46.14,62.49 45.97,62.31 45.95,62.31 45.94,62.32 40.59,62.32 40.29,62.02 U5.7 36.24,62.02 R26.2 ; 54.24,50.84 v1(53.84,51.24)
NAND_RE_B: length 24.1
  TOP w0.1: v1(50.08,57.65) 50.09,57.64 50.09,57.48 51.06,56.51 51.06,56.51 51.92,55.65 51.92,54.95 52.88,53.99 52.89,53.99 53.7,53.17 53.7,53.14 53.93,52.91 v1(53.93,52.84)
  BOTTOM w0.1: v1(53.93,52.84) 53.96,52.8 53.96,52.77 54.24,52.49 U1.R6 ; v1(50.08,57.65) 50.1,57.68 50.1,58.71 50.17,58.79 50.17,61.88 48.75,63.29 43,63.29 42.98,63.32 40.89,63.32 40.09,62.52 U5.8
NAND_WP_B: length 36.9
  TOP w0.1: v1(54.71,50.44) 54.71,50.57 54.28,51 54.28,51.4 54.05,51.64 53.67,51.64 53.43,51.88 53.43,52.22 53.2,52.46 52.87,52.46 52.67,52.67 52.67,53 52.69,53.03 52.69,53.3 51.31,54.68 51.31,55.38 49.44,57.25 49.44,58.22 51.66,60.44 51.66,60.54 52.35,61.22 v1(52.35,61.64)
  BOTTOM w0.1: 56.64,49.24 56.33,49.55 56.33,50.14 56.03,50.44 v1(54.71,50.44) ; v1(52.35,61.64) 52.29,61.64 45.9,68.03 U5.19 35.89,68.03 R27.1
NAND_WR_B: length 28.3
  TOP w0.1: v1(53.38,56.28) 53.45,56.28 55.04,54.68 55.04,53.09 54.98,53.03 54.98,52.69 55.46,52.22 v1(55.46,52.03)
  BOTTOM w0.1: v1(55.46,52.03) 55.46,52.02 U1.P8 ; U5.18 41.17,67.53 41.42,67.78 45.87,67.78 49.74,63.91 49.74,63.87 51.85,61.75 51.85,60.18 53.52,58.52 53.52,56.78 53.38,56.63 v1(53.38,56.28)
Net_72: length 0.6
  BOTTOM w0.1: 56.64,50.84 56.64,50.85 56.26,51.24 v1(56.26,51.29)
OC_BOT: length 11.5
  TOP w0.1: v1(28.14,28.13) 28.14,34.89 v1(27.83,35.2)
  BOTTOM w0.1: v1(27.83,35.2) 28.17,35.2 28.45,35.47 U25.19 ; U32.5 26.65,25.65 27.2,26.19 27.2,27.19 v1(28.14,28.13)
OC_MODEM: length 71.5
  TOP w0.1: v1(37.9,24.34) 37.56,24.34 37.2,24.7 37.2,25.16 37.21,25.17 37.21,25.92 36.57,26.56 29.03,26.56 26.51,29.08 26.51,31.63 26.69,31.81 v1(26.74,31.81) ; v1(81.4,14.29) 81.4,14.3 81.24,14.46 81.24,15.38 81.24,20.16 80.53,20.88 64.63,20.88 v1(64.62,20.89)
  INT1 w0.1: v1(64.62,20.89) 64.6,20.91 64.6,21.01 63.84,21.77 60.74,21.77 40.27,21.77 37.9,24.14 v1(37.9,24.34)
  BOTTOM w0.1: v1(81.4,14.29) 81.4,14.18 82.62,12.96 82.98,12.96 ; v1(26.74,31.81) 27.13,32.2 U25.13
OC_TOP: length 23.6
  TOP w0.1: v1(27.85,27.1) 27.81,27.1 27.02,27.9 27,27.9 26.3,28.59 26.3,34.29 v1(26.14,34.45) ; v1(26.6,19.95) 26.65,19.9 28.2,19.9 29.7,21.4 v1(29.7,21.7)
  BOTTOM w0.1: v1(26.14,34.45) 26.86,34.45 27.11,34.2 U25.17 ; U32.8 26.3,22.94 26.3,20.8 26.6,20.5 v1(26.6,19.95) ; v1(27.85,27.1) 27.85,25.8 29.7,23.95 v1(29.7,21.7)
OTG_GND: length 24.3
  TOP w0.3: 117.71,21.91 118.48,21.13 119.43,21.13 J7.5 ; 117.71,21.91 116.25,21.91 115.45,22.71 L4.1 ; 117.71,21.91 117.71,21.61 v1(117.37,21.27) ; 117.71,21.91 119,21.91 J7.S2 119.12,23.82 119.23,23.93 121.66,23.93 J7.S4 ; v2(122.12,15.63) 121.93,15.44 119.3,15.44 119.12,15.61 J7.S1 118.7,17.16 118.7,16.8 117.94,16.04 C304.2
  BOTTOM w0.5: v1(117.37,21.27) 117.37,19.34 J7.S1
  vias: v2(122.12,23.99)
PICOREAD_ANT1: length 8.1
  BOTTOM w0.3: D43.2 75.5,83.36 L27.1 73.21,83.12 73.21,80.89 72.8,80.48 U41.8
PICOREAD_ANT2: length 4.5
  BOTTOM w0.3: D43.1 79.61,82.98 L28.1 79.76,82.97 U41.9
PICOREAD_REC: length 4.2
  BOTTOM w0.1: U41.15 78.61,76.01 78.55,75.95 78.55,73.26 R179.1
PICOREAD_SPI_MISO: length 8.7
  TOP w0.1: v1(72.11,73.72) 72.11,74.01 72.33,74.23 72.33,74.24 72.53,74.44 v1(72.53,74.52)
  BOTTOM w0.1: RN9.6 71.77,73.12 72.11,73.46 v1(72.11,73.72) 72.24,73.84 72.82,73.84 72.96,73.98 73.49,73.98 73.7,73.77 73.7,73.42 73.74,73.38 73.74,73.35 73.97,73.12 RN8.7 ; v1(72.53,74.52) 72.65,74.4 73.26,74.4 73.27,74.42 73.72,74.42 73.97,74.67 73.97,75.63 73.59,76.01 73.37,76.01 73.36,76.01 U41.2
PICOREAD_SPI_MOSI: length 10.3
  TOP w0.1: v1(72.77,73.19) 73.11,73.19 73.13,73.17 73.47,73.17 73.47,73.18 73.77,73.18 74.5,73.91 74.5,76.26 v1(74.36,76.41)
  BOTTOM w0.1: U41.3 72.8,76.66 73.68,76.66 73.93,76.41 v1(74.36,76.41) ; 72.35,72.12 72.77,72.53 v1(72.77,73.19) ; 72.35,72.12 RN9.8 ; 72.35,72.12 RN8.5
PICOREAD_SPI_SCK: length 8.4
  BOTTOM w0.1: 71.39,73.82 71.39,74.7 71.28,74.8 71.28,77.14 71.46,77.31 U41.4 ; 71.39,73.82 71.68,74.12 72.81,74.12 72.88,74.18 73.69,74.18 74.14,73.74 RN8.8 ; 71.39,73.82 RN9.5
PICOREAD_SPI_SS: length 5.7
  TOP w0.1: v1(73.09,74.81) 73.09,74.78 73.09,74.78 73.09,73.8 73.3,73.6 v1(73.3,73.58)
  BOTTOM w0.1: v1(73.09,74.81) 73.09,74.95 72.8,75.24 U41.1 ; RN8.6 74.02,72.62 73.54,73.1 73.54,73.3 73.3,73.54 v1(73.3,73.58) 73.28,73.6 72.6,73.6 71.62,72.62 RN9.7
PICOREAD_VDDA: length 12.6
  TOP w0.3: v1(74.7,77.79) 74.66,77.75 74.22,77.75 74.02,77.94 R204.2 ; v1(81.19,77.2) 81.19,76.55 81.26,76.55 C274.1
  INT1 w0.5: v1(81.19,77.2) 78.23,77.2 77.63,77.79 v1(74.7,77.79)
  BOTTOM w0.3: 81.47,76.66 C175.1 81.49,76.56 C273.1 ; 81.47,76.66 81.19,76.94 v1(81.19,77.2) ; 81.47,76.66 81.45,76.65 79.77,76.65 U41.14
PICOREAD_XTAL1: length 10.6
  TOP w0.1: Y9.1 78.55,75.7 ; 78.55,75.7 77.41,76.84 C243.1 ; 78.55,75.7 78.55,77.85 78.65,77.95 81.7,77.95 v1(81.8,78.05)
  BOTTOM w0.1: U41.12 80.82,77.97 80.83,77.95 81.7,77.95 v1(81.8,78.05)
PICOREAD_XTAL2: length 7.3
  TOP w0.1: C244.1 76.45,80.21 78.49,80.21 78.65,80.05 Y9.2 78.7,80 79.65,79.06 79.65,78.7 79.7,78.65 81.12,78.65 v1(81.15,78.62)
  BOTTOM w0.1: U41.11 v1(81.15,78.62)
PSWITCH: length 28.9
  TOP w0.1: v1(61.18,26.71) 60.85,26.71 57.78,29.78 57.78,32.96 58.21,33.39 58.21,38.05 58.22,38.06 58.22,38.7 58.21,38.72 58.21,39 v1(58.41,39.21) ; R39.1 67.52,20.25 68.73,20.25 v1(68.8,20.19)
  BOTTOM w0.1: 58.24,41.24 58.19,41.18 58.19,40.14 58.2,40.13 58.2,39.67 58.31,39.56 58.31,39.31 v1(58.41,39.21) ; v1(61.18,26.71) 61.18,25.63 65.91,20.91 66.24,20.91 66.24,20.91 68.23,20.91 68.8,20.34 v1(68.8,20.19)
RESET_IN_B: length 131.5
  TOP w0.1: v1(96.93,85.38) 95.5,85.38 93.25,87.62 93.25,102.29 SW3.1 93.55,102.55 98.76,102.55 ; v1(89.77,61.94) 89.77,62.34 89.77,66.45 91.05,67.72 91.05,68.43 v1(91.23,68.62) ; 98.76,102.55 SW3.3 ; 98.76,102.55 98.76,101.07 98.5,100.82 R45.1 ; v1(84.08,38.44) 83.88,38.24 83.88,33.84 83.67,33.63 83.67,33.63 78.94,28.9 62.71,28.9 61.88,29.73 61.88,30.34 60.79,31.43 v1(60.79,32.81) ; v1(84.27,40.84) 84.32,40.88 85.58,40.88 86.47,41.78 v1(86.47,42.23)
  INT1 w0.1: v1(91.23,68.62) 91.58,68.62 96.05,73.09 96.05,84.53 96.89,85.38 v1(96.93,85.38) ; v1(86.47,42.23) 86.34,42.35 86.34,45.08 83.64,47.78 83.64,47.81 82.96,48.49 82.96,54.05 83.45,54.05 84.1,54.7 84.1,56.68 89.36,61.94 v1(89.77,61.94)
  BOTTOM w0.1: 60.64,41.24 60.64,39.26 60.33,38.94 60.33,38 61.24,37.09 61.28,37.09 61.78,36.59 61.79,36.59 62.05,36.34 62.05,35.83 61.77,35.55 61.38,35.55 60.79,34.96 v1(60.79,32.81) ; 89.27,39.62 87.3,39.62 86.51,40.4 86.51,42.19 v1(86.47,42.23) ; v1(84.27,40.84) 84.18,40.84 83.89,40.55 83.89,38.63 v1(84.08,38.44)
RXER/PHYAD0: length 2.5
  BOTTOM w0.1: U3.10 34.09,48.33 R14.1 35.27,48.65 R16.2
SAIF0_BITCLK: length 51.5
  INT1 w0.1: v1(94.66,28.4) 94.58,28.31 85.67,28.31 82.71,31.27 74.78,31.27 72.62,33.43 72.45,33.43 72.45,33.43 69.72,33.43 67.66,35.49 60.99,35.49 58.58,37.9 58.58,38.8 58.82,39.04 58.82,39.51 57.85,40.48 57.85,40.64 57.16,41.32 57.16,42.28 56.59,42.86 56.07,42.86 55.85,43.07 55.85,43.41 55.63,43.64 55.31,43.64 55.1,43.84 55.1,45.1 v1(54.58,45.61)
  BOTTOM w0.1: v1(54.58,45.61) 54.58,45.59 54.94,45.24 55.05,45.24 ; v1(94.66,28.4) 94.68,28.38 94.68,28.37 94.7,28.34 R202.1
SAIF0_DIN: length 48.6
  INT1 w0.1: v1(56.24,44.06) 56.24,44.02 56.7,43.57 56.7,43.4 56.69,43.39 56.69,43.04 57.37,42.37 57.37,41.4 57.91,40.86 58.81,40.86 59.06,40.6 59.06,37.7 61.08,35.69 67.74,35.69 69.8,33.62 72.37,33.62 72.37,33.63 72.7,33.63 74.87,31.47 82.79,31.47 85.29,28.97 94.49,28.97 v1(94.61,29.09)
  BOTTOM w0.1: R199.1 94.77,29.25 v1(94.61,29.09) ; v1(56.24,44.06) 56.24,44.11 55.92,44.44 U1.E8
SAIF0_DOUT: length 52.7
  INT1 w0.1: v1(54.62,43.27) 54.62,43.26 54.62,43 55.07,42.55 55.07,42.06 55.97,41.17 56.75,41.17 57.41,40.5 57.41,39.03 58.04,38.41 58.04,37.91 58.14,37.81 58.14,37.77 60.83,35.09 67.49,35.09 69.56,33.02 72.41,33.02 72.7,32.74 72.71,32.74 74.58,30.87 82.54,30.87 85.62,27.78 91.88,27.78 92.61,27.05 v1(93.73,27.05)
  BOTTOM w0.1: v1(54.62,43.27) 54.62,43.28 54.62,43.92 55.05,44.34 55.05,44.44 ; v1(93.73,27.05) 94.09,27.42 94.09,29.25 95.02,30.16 R200.1
SAIF0_LRCLK: length 51.8
  INT1 w0.1: v1(53.86,45.57) 53.87,45.57 53.93,45.57 54.89,44.6 54.89,43.57 55.02,43.44 55.02,43.07 55.26,42.83 55.63,42.83 55.88,42.58 55.88,42.27 56.78,41.37 56.83,41.37 57.62,40.59 57.62,39.16 58.34,38.43 58.34,37.86 60.91,35.28 67.57,35.28 69.63,33.22 70.17,33.22 72.54,33.22 74.69,31.07 82.62,31.07 85.71,27.98 94.14,27.98 v1(94.64,27.48)
  BOTTOM w0.1: U1.G6 54.23,46.03 53.86,45.66 v1(53.86,45.57) ; 95.31,27.5 94.67,27.5 94.64,27.48 v1(94.64,27.48)
SAIF0_MCLK: length 55.5
  INT1 w0.1: v1(94.65,26.66) 94.64,26.65 92.45,26.65 92.04,27.06 92.03,27.06 91.79,27.29 91.79,27.31 91.63,27.47 85.73,27.47 85.63,27.57 85.54,27.57 82.46,30.66 82.37,30.66 82.36,30.67 74.48,30.67 72.62,32.53 72.61,32.53 72.32,32.82 69.47,32.82 67.41,34.88 60.74,34.88 57.94,37.69 57.94,37.72 57.64,38.03 57.17,38.03 57,38.19 57,38.78 57.1,38.88 57.1,40.44 56.63,40.92 54.79,40.92 54.23,41.48 54.23,42.18 54.24,42.2 54.24,43.07 54.21,43.1 54.21,43.66 53.45,44.41 53.45,45.93 53.86,46.33 v1(53.86,46.4)
  BOTTOM w0.1: v1(53.86,46.4) 53.87,46.41 54.35,46.41 54.7,46.06 54.85,46.06 54.88,46.03 55.05,46.03 ; R203.1 v1(94.65,26.66)
SPI2_MISO: length 73
  INT1 w0.1: v1(68.75,70.94) 68.75,70.68 67.96,69.89 67.49,69.89 66.04,68.44 61.14,68.44 58.15,71.43 50.54,71.43 40.61,61.5 40.61,57.69 40.61,56.6 39.91,55.9 39.91,46.27 40.56,45.62 v1(40.56,43.66)
  BOTTOM w0.1: U1.B4 52.35,42.03 52.35,42.03 52.01,42.03 52.01,42.03 U1.B3 51.84,41.92 51.66,41.74 51.63,41.74 51.41,41.51 51.41,41.16 50.48,40.22 49.6,40.22 49.32,40.5 49.32,41.02 49.38,41.08 49.38,41.41 49.16,41.63 49.15,41.63 48.77,42.02 48.77,43.55 48.02,44.3 45.58,44.3 44.89,43.61 40.62,43.61 v1(40.56,43.66) ; v1(68.75,70.94) 68.75,72.29 69.58,73.12 RN9.3
SPI2_MOSI: length 70.4
  INT1 w0.1: v1(41.83,44.01) 41.83,45.04 40.31,46.56 40.31,55.73 41.01,56.44 41.01,57.02 41.01,61.34 50.7,71.03 57.99,71.03 60.97,68.04 63.47,68.04 63.47,68.04 64.26,68.04 64.41,68.04 66.2,68.04 67.65,69.49 68.13,69.49 68.9,70.26 69.5,70.26 69.5,70.26 69.68,70.26 v1(69.89,70.48)
  BOTTOM w0.1: v1(69.89,70.48) 69.89,71.28 70.39,71.76 RN9.1 ; v1(41.83,44.01) 41.97,43.88 44.86,43.88 45.5,44.51 48.09,44.51 48.96,43.63 48.96,42.1 49.23,41.83 49.24,41.83 49.59,41.48 49.59,41.15 49.58,41.13 49.58,40.99 49.52,40.94 49.52,40.62 49.72,40.42 50.21,40.42 50.71,40.93 50.71,41.33 50.92,41.54 51.14,41.54 51.48,41.88 51.48,42.34 51.84,42.71 51.84,42.84
SPI2_SCK: length 73.5
  INT1 w0.1: v1(68.16,70.82) 68.14,70.79 68.14,70.34 67.88,70.09 66.66,70.09 66.65,70.09 66.32,70.09 65.27,69.04 65.27,69.04 64.93,68.69 64.93,68.69 64.88,68.64 61.22,68.64 58.23,71.63 50.45,71.63 40.41,61.59 40.41,57.6 40.41,56.68 39.71,55.98 39.71,46.15 40.3,45.56 40.3,44.72 40.13,44.56 40.13,43.52 40.86,42.8 41.2,42.8 41.33,42.68 v1(41.42,42.68)
  BOTTOM w0.1: 51.84,41.24 51.79,41.24 50.56,40.01 49.53,40.01 48.37,41.18 48.37,43.39 47.85,43.9 45.8,43.9 45.09,43.19 41.99,43.19 41.48,42.68 v1(41.42,42.68) ; v1(68.16,70.82) 68.14,70.84 68.14,72.7 69.06,73.62 RN9.4
SPI2_SS: length 71.2
  TOP w0.1: v1(52.18,42.43) 51.36,42.43 50.27,41.34 49.07,41.34 v1(48.97,41.24)
  INT1 w0.1: v1(41.02,43.2) 41.02,45.5 40.11,46.42 40.11,55.82 40.81,56.52 40.81,57.11 40.81,61.42 50.62,71.23 58.07,71.23 61.05,68.24 64,68.24 64.35,68.24 66.12,68.24 67.57,69.69 68.04,69.69 68.82,70.46 69.11,70.46 v1(69.31,70.66)
  BOTTOM w0.1: RN9.2 70.09,72.62 69.31,71.84 v1(69.31,70.66) ; v1(52.18,42.43) 52.18,42.46 52.56,42.84 52.64,42.84 ; v1(48.97,41.24) 48.56,41.65 48.56,43.47 47.93,44.1 45.66,44.1 44.97,43.41 43.39,43.41 43.37,43.38 41.72,43.38 41.61,43.28 41.11,43.28 v1(41.02,43.2)
TOUCH_RESET: length 1.6
  TOP w0.1: R92.1 101.64,58.13 J13.33
UART0_CTS: length 45.5
  TOP w0.1: v1(44.37,38.59) 44.37,38.59 44.25,38.59 42.7,37.04 39.1,37.04 38.77,37.04 38.43,37.04 35.56,37.04 29.72,37.04 29.41,36.73 29.08,36.73 27.92,36.73 25.78,36.73 25.63,36.58 25.12,36.58 v1(25.11,36.59) ; v1(22.39,31.61) 22.7,31.3 J20.44 ; v1(49.61,48.03) 48.73,47.16 48.36,47.16 47.92,46.71 47.92,45.85 45.38,43.31 45.38,42.87 v1(45.38,42.86)
  BOTTOM w0.1: v1(22.39,31.61) 22.49,31.71 22.49,33.98 v1(25.11,36.59) ; v1(44.37,38.59) 44.43,38.59 45.19,39.35 45.19,40.97 45.7,41.48 45.7,41.7 45.84,41.85 45.84,42.4 45.38,42.86 v1(45.38,42.86) ; v1(49.61,48.03) 49.61,47.97 49.94,47.64 49.94,47.51 50.12,47.33 50.37,47.33 50.74,47.7 50.74,47.76 51.03,48.05 53.52,48.05 53.93,47.63 U1.J6
UART0_RTS: length 51.2
  TOP w0.1: v1(43.89,39.59) 43.89,39.53 41.8,37.44 38.94,37.44 29.55,37.44 29.24,37.13 26.17,37.13 25.77,37.53 25.43,37.53 25.41,37.52 v1(25.12,37.52) ; v1(17.27,36.19) 17.27,36.19 16.86,35.78 16.86,31.24 16.52,30.9 J20.45 ; v1(53.05,47.26) 52.49,46.72 52.49,46.56 51.88,45.95 48.38,45.95 46.28,43.85 46.28,43.19 45.54,42.45 44.92,42.45 44.88,42.41 44.88,42.41 v1(44.89,42.41)
  BOTTOM w0.1: 55.05,47.63 54.66,47.25 53.05,47.25 v1(53.05,47.26) ; v1(17.27,36.19) 17.29,36.19 18.43,37.33 19.2,37.33 19.25,37.28 19.59,37.28 19.64,37.33 24.94,37.33 v1(25.12,37.52) ; v1(44.89,42.41) 44.88,42.41 44.88,42.41 44.6,42.13 44.6,40.04 44.15,39.59 v1(43.89,39.59)
UART0_RX: length 42.4
  TOP w0.1: v1(22.39,30.79) 22.69,30.5 J20.46 ; v1(47.08,43.19) 47.08,43.8 48.73,45.45 52.79,45.45 v1(52.97,45.63) ; v1(25.19,35.96) 25.34,35.96 25.91,36.53 27.83,36.53 29,36.53 29.49,36.53 29.8,36.84 35.14,36.84 38.34,36.84 38.85,36.84 39.18,36.84 42.78,36.84 44.08,38.14 44.57,38.14 44.97,38.53 v1(44.98,38.53)
  BOTTOM w0.1: v1(47.08,43.19) 46.54,43.19 46.05,42.69 46.05,41.77 45.9,41.62 45.9,41.05 45.39,40.54 45.39,38.94 v1(44.98,38.53) ; v1(22.39,30.79) 23.2,31.59 23.2,33.99 25.18,35.96 v1(25.19,35.96) ; 53.45,46.03 53.04,45.63 v1(52.97,45.63)
UART0_TX: length 49.5
  TOP w0.1: v1(25.59,37.13) 25.62,37.13 25.82,36.93 29.33,36.93 29.64,37.24 38.52,37.24 38.52,37.24 39.02,37.24 42.17,37.24 43.9,38.97 v1(43.9,38.97) ; J20.47 16.85,30.1 17.05,30.31 17.05,35.09 17.3,35.32 v1(17.3,35.34) ; v1(45.44,42.04) 45.5,42.1 45.5,42.12 46.48,43.1 46.48,43.77 48.41,45.7 52.29,45.7 53.01,46.42 v1(53.1,46.42)
  BOTTOM w0.1: 53.45,46.84 53.1,46.49 v1(53.1,46.42) ; v1(17.3,35.34) 17.32,35.34 17.64,35.67 17.64,35.9 18.79,37.04 21.1,37.04 25.51,37.04 v1(25.59,37.13) ; v1(43.9,38.97) 43.9,38.97 43.91,38.96 44.15,38.96 44.91,39.72 44.91,41.57 45.38,42.04 v1(45.44,42.04)
UART1_RX: length 99.6
  TOP w0.1: v1(45.62,57.37) 45.62,56.66 48.27,54.02 48.27,53.34 50.2,51.41 50.2,50.8 51.35,49.65 52.15,49.65 52.16,49.64 52.16,49.63 52.16,49.63 v1(52.16,49.63) ; v1(91.15,45.88) 89.91,45.88 88.29,47.5 85.27,47.5 84.17,48.6 84.17,48.6 81.45,51.32 81.45,57.36 80.48,58.34 80.48,59.33 80.46,59.34 v1(80.45,59.34)
  INT1 w0.1: v1(45.62,57.37) 45.62,57.79 44.24,59.17 44.24,62.88 51.15,69.78 52.12,69.78 52.12,69.79 52.62,69.79 52.62,69.78 56.66,69.78 56.66,69.79 57.23,69.79 60.34,66.67 60.94,66.67 61.27,66.67 61.6,66.67 65.99,66.67 66.13,66.67 66.38,66.67 66.38,66.68 72.88,66.68 v1(73.34,67.13)
  BOTTOM w0.1: R157.2 104.07,42.82 102.95,41.7 98.85,41.7 98.35,42.2 98.35,43.29 97.08,44.57 97.08,44.58 95.78,45.88 v1(91.15,45.88) ; v1(52.16,49.63) 52.16,49.63 52.16,49.63 52.16,49.64 52.17,49.64 52.57,49.24 52.64,49.24 ; v1(73.34,67.13) 73.34,66.47 74.64,65.18 74.64,64.47 79.8,59.31 80.32,59.31 80.38,59.37 80.48,59.37 80.48,59.34 v1(80.45,59.34)
UART1_TX: length 101.6
  TOP w0.1: v1(79.97,59.82) 79.98,59.82 79.99,59.81 79.99,58.44 81.25,57.18 81.25,51.24 83.97,48.52 83.97,48.51 85.18,47.3 88.2,47.3 90.08,45.42 v1(91.62,45.42) ; v1(45.02,57.54) 45.02,57.03 45.42,56.63 45.42,56.58 48.06,53.94 48.06,53.26 49.99,51.33 49.99,50.72 51.27,49.44 51.77,49.44 52.16,49.05 52.16,49 v1(52.24,48.92)
  INT1 w0.1: v1(74.44,67.21) 74.11,67.54 73.17,67.54 72.5,66.88 66.3,66.88 66.3,66.87 61.52,66.87 60.42,66.87 57.3,70 51.08,70 44.05,62.96 44.05,59.09 45.02,58.11 45.02,57.54 v1(45.02,57.54)
  BOTTOM w0.1: v1(79.97,59.82) 79.91,59.76 79.63,59.76 74.87,64.53 74.87,66.96 74.61,67.21 v1(74.44,67.21) ; R156.2 104.8,41.94 104.3,41.45 98.75,41.45 98.05,42.15 98.05,43.31 96.88,44.48 96.88,44.5 95.73,45.65 91.84,45.65 v1(91.62,45.42) ; v1(52.24,48.92) 52.64,48.51 U1.K4
USB0_DM: length 68.5
  TOP w0.15: v1(109.37,19.64) 109.37,19.28 109.62,19.03 L29.1
  INT1 w0.15: v1(56.57,38.31) 56.35,38.09 56.35,33.03 60.16,29.23 61.88,29.23 63.07,28.04 77.99,28.04 80.7,25.34 98.57,25.34 98.72,25.19 98.72,25.19 98.91,25 98.91,25 103.91,19.99 109.03,19.99 v1(109.37,19.64)
  BOTTOM w0.15: v1(56.57,38.31) 56.52,38.37 56.52,38.63 57.35,39.47 57.35,41.15 57.45,41.24
USB0_DP: length 69.9
  TOP w0.15: L29.4 109.97,20.07 108.8,20.07 108.5,19.77 v1(108.5,19.56)
  INT1 w0.15: v1(55.93,38.54) 55.93,38.44 56.1,38.27 56.1,38.19 56.1,32.93 60.05,28.98 61.78,28.98 62.96,27.79 77.89,27.79 80.6,25.09 98.47,25.09 98.47,25.08 98.66,24.9 98.66,24.89 103.81,19.74 108.33,19.74 v1(108.5,19.56)
  BOTTOM w0.15: v1(55.93,38.54) 56.05,38.66 56.06,38.66 56.32,38.92 56.45,38.92 57.1,39.57 57.1,41.69 57.45,42.03
USB0_ID: length 107
  TOP w0.1: 47.16,47.03 47.16,45.79 46.12,44.75 46.12,44.75 44.43,43.05 44.43,42.79 v1(44.39,42.76) ; 47.16,47.03 R17.2 ; 47.16,47.03 47.7,47.57 48.79,47.57 49.02,47.81 49.02,48.1 49.5,48.57 50.89,48.57 51.27,48.2 52.71,48.2 52.96,48.46 53.17,48.46 53.45,48.74 53.45,49.28 v1(53.81,49.63) ; J7.4 119.43,20.44 116.51,20.44 112.55,24.4 v1(98.05,24.4)
  INT1 w0.1: v1(98.05,24.4) 97.53,23.88 92.48,23.88 91.32,22.73 89.22,22.73 89.21,22.74 83.79,22.74 83.56,22.97 83.56,22.97 83.07,23.46 61.66,23.46 60.94,24.18 59.25,24.18 57.73,25.7 57.73,26.06 v1(56.07,27.72)
  BOTTOM w0.1: v1(56.07,27.72) 56.06,27.72 55.01,28.76 54.6,28.76 51.35,32.01 51.35,32.01 51.02,32.35 50.64,32.35 50.25,32.35 50.25,32.34 49.64,32.34 45.98,36 45.98,36.57 45.99,36.57 45.99,36.57 45.99,36.75 45.99,36.75 45.99,37.03 45.96,37 45.96,37.06 45.85,37.18 45.78,37.18 44.84,38.12 44.13,38.12 43.5,38.76 43.5,39.14 43.5,39.14 43.5,39.4 43.49,39.42 43.49,39.75 43.5,39.77 43.5,41.34 44.43,42.27 44.43,42.73 44.39,42.77 44.39,42.76 v1(44.39,42.76) ; U1.K8 55.48,48.44 55.05,48.87 54.19,48.87 53.81,49.24 v1(53.81,49.63)
USB1_DM: length 46.9
  INT1 w0.15: v1(34.99,33.84) 34.99,33.52 35.11,33.4 35.11,30.96 38.32,27.75 38.32,26.01 41.33,23 52.6,23 53.27,23.67 53.27,34.24 54.2,35.16 54.2,37.96 54.73,38.49 v1(54.73,38.77)
  BOTTOM w0.15: v1(34.99,33.84) 34.85,33.7 33.33,33.7 U25.30 ; U1.B8 55.84,41.7 55.49,41.35 55.49,40.89 55.38,40.77 55.38,40.76 55.28,40.67 55.28,39.31 54.77,38.8 54.76,38.8 v1(54.73,38.77)
USB1_DP: length 45.9
  INT1 w0.15: v1(34.64,33.27) 34.86,33.05 34.86,30.86 38.07,27.65 38.07,25.91 41.23,22.75 52.7,22.75 53.52,23.57 53.52,34.13 54.45,35.06 54.45,37.57 v1(55.24,38.37)
  BOTTOM w0.15: v1(55.24,38.37) 55.24,38.92 55.53,39.21 55.53,40.56 55.62,40.66 55.62,40.66 55.74,40.78 55.74,41.13 55.84,41.24 ; U25.31 33.39,33.27 v1(34.64,33.27)
USB2SER_RX: length 3.7
  TOP w0.1: v1(107.19,9.26) 107.19,9.72 U34.19
  BOTTOM w0.1: Q18.2 109.16,10.61 107.8,9.25 107.2,9.25 v1(107.19,9.26)
USB2SER_TX: length 5.7
  TOP w0.1: 107.37,10.54 107.89,10.54 108.08,10.36 v1(108.08,10.21)
  BOTTOM w0.1: 108.08,10.21 108.08,10.2 108.09,10.19 ; 108.08,10.21 v1(108.08,10.21) ; 108.08,10.21 108.08,12.38 107.83,12.63 107.83,13.41 108.22,13.8 Q20.2
USB_BOT_DM: length 38.9
  INT1 w0.15: v1(31.4,5.95) 31.3,5.85 31.3,5.8 30.88,5.38 24.39,5.38 21.92,7.84 21.92,17.26 23.54,18.88 24.83,18.88 25.94,19.99 25.94,25.4 26.77,26.24 28.26,26.24 v1(29.94,27.92)
  BOTTOM w0.15: v1(31.4,5.95) 31.4,6.85 L32.1 ; U25.6 30.05,29.27 29.93,29.15 29.93,28.46 29.77,28.3 29.77,28.09 v1(29.94,27.92)
USB_BOT_DP: length 40
  INT1 w0.15: v1(29.27,27.93) 29.27,27.6 28.15,26.49 26.67,26.49 25.69,25.5 25.69,20.09 24.73,19.13 23.64,19.13 23.44,19.14 21.67,17.37 21.67,7.74 24.29,5.12 24.49,5.12 31.23,5.12 32.05,5.95 v1(32.1,5.95)
  BOTTOM w0.15: v1(29.27,27.93) 29.27,27.93 29.27,28.16 29.68,28.57 29.68,29.15 29.55,29.27 U25.7 ; v1(32.1,5.95) 32.2,6.05 32.2,6.78 32.29,6.87
USB_DEBUG_DM: length 11
  TOP w0.15: U34.14 104.16,8.88 104.16,6.89 105.27,5.78 112.32,5.78 L34.1
USB_DEBUG_DP: length 10.8
  TOP w0.15: L34.4 111.91,6.58 111.36,6.03 105.37,6.03 104.41,7 104.41,8.88 U34.15
USB_EXTAL: length 4.3
  TOP w0.1: U34.22 108.32,11.84 R47.2 108.75,11.57 109.35,11.57 Y8.3 109.82,13.22 C148.1
USB_HUB_RST_B: length 80.2
  TOP w0.1: v1(32.05,36.35) 31.16,36.35 30.74,35.94 30.23,35.94 29.84,36.33 27.75,36.33 26.2,36.33 v1(25.21,35.34)
  INT1 w0.1: v1(26.21,45.93) 26.21,50.56 29.02,53.37 29.38,53.37 30.72,54.71 30.73,54.71 31.99,55.96 34.17,55.96 34.19,55.97 34.42,55.97 34.43,55.96 34.93,55.96 35.28,55.96 35.61,55.96 36.49,55.96 37.89,57.36 37.89,57.38 38.34,57.83 38.34,61.02 43.91,66.58 43.91,67.85 43.9,67.85 43.9,68.18 44.64,68.91 44.64,69.2 46.31,70.88 v1(46.31,70.94)
  BOTTOM w0.1: v1(32.05,36.35) 32.05,36.35 U25.26 ; U17.15 63.48,66.74 63.1,67.12 63.1,67.12 62.17,68.06 62.17,70.3 61.55,70.93 61.42,71.06 59.87,72.6 59.56,72.6 59.55,72.6 47.6,72.6 46.81,71.82 46.81,71.44 v1(46.31,70.94) ; v1(26.21,45.93) 26.58,45.93 27.52,44.99 27.52,38.93 26.87,38.28 26.87,37.03 25.21,35.38 v1(25.21,35.34)
USB_MODEM_DM: length 46.1
  INT1 w0.15: v1(69.34,15.63) 69.19,15.78 63.19,15.78 59.66,19.31 38.83,19.31 33.45,24.68 33.45,27.13 33.19,27.4 33.19,27.77 33.2,27.78 v1(33.2,28)
  BOTTOM w0.15: U25.1 32.55,29.13 32.85,28.82 32.85,28.34 v1(33.2,28) ; L33.4 69.5,15.47 v1(69.34,15.63)
USB_MODEM_DP: length 46.6
  INT1 w0.15: v1(33.7,27.53) 33.7,24.78 38.93,19.56 59.77,19.56 63.29,16.03 69.08,16.03 v1(69.29,16.24)
  BOTTOM w0.15: v1(69.29,16.24) 69.44,16.09 69.9,16.09 L33.1 ; v1(33.7,27.53) 33.01,27.53 32.6,27.93 32.6,28.72 32.05,29.27 U25.2
USB_TOP_DM: length 10
  TOP w0.15: v1(31.7,21.99) 31.7,21.95 31.64,21.9 31.64,21.02 31.33,20.71 L31.1
  INT1 w0.15: v1(31.98,27.87) 31.98,23.03 32.15,22.87 32.15,22.44 v1(31.7,21.99)
  BOTTOM w0.15: v1(31.98,27.87) 31.59,28.27 31.59,29.28 31.55,29.31 U25.3
USB_TOP_DP: length 10
  TOP w0.15: v1(31.72,22.67) 31.73,22.65 31.73,22.64 32.12,22.25 32.12,20.56 L31.4
  INT1 w0.15: v1(31.34,27.87) 31.38,27.87 31.73,27.51 31.73,22.69 v1(31.72,22.67)
  BOTTOM w0.15: U25.4 31.05,29.46 31.34,29.17 v1(31.34,27.87)
USB_XTAL: length 6.5
  TOP w0.1: U34.21 108.11,11.19 108.44,10.86 110.94,10.86 111.42,10.38 Y8.1 111.42,8.74 C149.1
